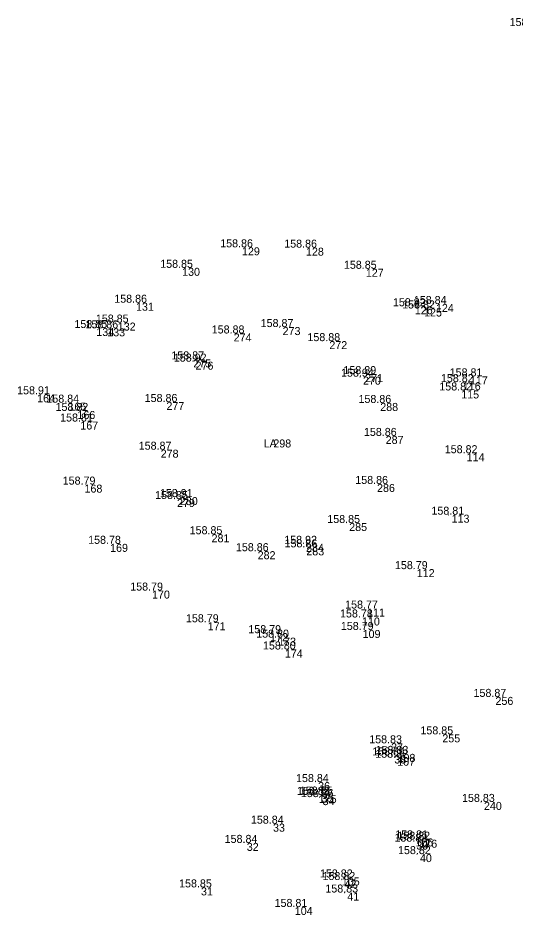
# Model space of a CAD drawing. Extents: x -583198 to -582878, y -1211024 to -1210637.
# Drawn here: x -583173.33 to -583157.8, y -1210989.22 to -1210961.21 of the extents above; entities that cross this region are included whole.
import ezdxf

# ---------------------------------------------------------------- set-up
doc = ezdxf.new("R2010")
doc.units = 0
for name, color, linetype in [('1   Kódy', 7, 'Continuous'), ('4   Body podrobné', 7, 'Continuous'), ('5   Body podrobné - čísla', 7, 'Continuous'), ('6   Body podrobné - výšky', 7, 'Continuous')]:
    doc.layers.add(name, color=color, linetype=linetype)

msp = doc.modelspace()

# ---------------------------------------------------------------- linework, layer by layer
at = {"layer": '4   Body podrobné'}
for p, q in [((-583166.42, -1210968.37), (-583166.419, -1210968.37)), ((-583164.42, -1210968.38), (-583164.419, -1210968.38)), ((-583168.29, -1210969.01), (-583168.289, -1210969.01)), ((-583162.55, -1210969.04), (-583162.549, -1210969.04)), ((-583169.73, -1210970.1), (-583169.729, -1210970.1)), ((-583161.02, -1210970.21), (-583161.019, -1210970.21)), ((-583160.36, -1210970.14), (-583160.359, -1210970.14)), ((-583160.73, -1210970.28), (-583160.729, -1210970.28)), ((-583170.3, -1210970.72), (-583170.299, -1210970.72)), ((-583170.97, -1210970.89), (-583170.969, -1210970.89)), ((-583170.63, -1210970.9), (-583170.629, -1210970.9)), ((-583165.15, -1210970.86), (-583165.149, -1210970.86)), ((-583166.68, -1210971.06), (-583166.679, -1210971.06)), ((-583163.69, -1210971.3), (-583163.689, -1210971.3)), ((-583167.94, -1210971.87), (-583167.939, -1210971.87)), ((-583167.87, -1210971.94), (-583167.869, -1210971.94)), ((-583162.64, -1210972.41), (-583162.639, -1210972.41)), ((-583162.57, -1210972.33), (-583162.569, -1210972.33)), ((-583159.3, -1210972.4), (-583159.299, -1210972.4)), ((-583159.52, -1210972.58), (-583159.519, -1210972.58)), ((-583172.82, -1210972.96), (-583172.819, -1210972.96)), ((-583159.57, -1210972.84), (-583159.569, -1210972.84)), ((-583171.84, -1210973.22), (-583171.839, -1210973.22)), ((-583168.78, -1210973.2), (-583168.779, -1210973.2)), ((-583162.1, -1210973.23), (-583162.099, -1210973.23)), ((-583171.56, -1210973.48), (-583171.559, -1210973.48)), ((-583171.47, -1210973.81), (-583171.469, -1210973.81)), ((-583165.44, -1210974.37), (-583165.439, -1210974.37)), ((-583161.93, -1210974.26), (-583161.929, -1210974.26)), ((-583168.96, -1210974.69), (-583168.959, -1210974.69)), ((-583159.4, -1210974.8), (-583159.399, -1210974.8)), ((-583171.34, -1210975.78), (-583171.339, -1210975.78)), ((-583162.2, -1210975.76), (-583162.199, -1210975.76)), ((-583168.45, -1210976.23), (-583168.449, -1210976.23)), ((-583168.36, -1210976.17), (-583168.359, -1210976.17)), ((-583159.87, -1210976.72), (-583159.869, -1210976.72)), ((-583163.07, -1210976.98), (-583163.069, -1210976.98)), ((-583167.37, -1210977.33), (-583167.369, -1210977.33)), ((-583170.54, -1210977.63), (-583170.539, -1210977.63)), ((-583164.42, -1210977.63), (-583164.419, -1210977.63)), ((-583164.41, -1210977.74), (-583164.409, -1210977.74)), ((-583165.93, -1210977.86), (-583165.929, -1210977.86)), ((-583160.96, -1210978.42), (-583160.959, -1210978.42)), ((-583169.23, -1210979.09), (-583169.229, -1210979.09)), ((-583162.51, -1210979.65), (-583162.509, -1210979.65)), ((-583162.67, -1210979.93), (-583162.669, -1210979.93)), ((-583167.49, -1210980.08), (-583167.489, -1210980.08)), ((-583165.54, -1210980.42), (-583165.539, -1210980.42)), ((-583165.29, -1210980.56), (-583165.289, -1210980.56)), ((-583162.65, -1210980.32), (-583162.649, -1210980.32)), ((-583165.08, -1210980.93), (-583165.079, -1210980.93)), ((-583158.5, -1210982.41), (-583158.499, -1210982.41)), ((-583160.16, -1210983.58), (-583160.159, -1210983.58)), ((-583161.76, -1210983.86), (-583161.759, -1210983.86)), ((-583161.56, -1210984.19), (-583161.559, -1210984.19)), ((-583161.66, -1210984.24), (-583161.659, -1210984.24)), ((-583161.57, -1210984.31), (-583161.569, -1210984.31)), ((-583164.04, -1210985.07), (-583164.039, -1210985.07)), ((-583164.02, -1210985.47), (-583164.019, -1210985.47)), ((-583163.93, -1210985.46), (-583163.929, -1210985.46)), ((-583163.9, -1210985.54), (-583163.899, -1210985.54)), ((-583158.86, -1210985.69), (-583158.859, -1210985.69)), ((-583165.45, -1210986.37), (-583165.449, -1210986.37)), ((-583166.27, -1210986.97), (-583166.269, -1210986.97)), ((-583161, -1210986.83), (-583160.999, -1210986.83)), ((-583160.97, -1210986.93), (-583160.969, -1210986.93)), ((-583160.88, -1210986.87), (-583160.879, -1210986.87)), ((-583160.86, -1210987.32), (-583160.859, -1210987.32)), ((-583163.3, -1210988.05), (-583163.299, -1210988.05)), ((-583163.22, -1210988.13), (-583163.219, -1210988.13)), ((-583167.7, -1210988.36), (-583167.699, -1210988.36)), ((-583163.13, -1210988.52), (-583163.129, -1210988.52)), ((-583164.77, -1210988.97), (-583164.769, -1210988.97))]:
    msp.add_line(p, q, dxfattribs=at)

# ---------------------------------------------------------------- texts
at = {"layer": '1   Kódy'}
msp.add_text('LA', height=0.25, dxfattribs=at).set_placement((-583165.65, -1210974.62))
at = {"layer": '5   Body podrobné - čísla'}
for s, p in [(' 129', (-583166.42, -1210968.62)), (' 128', (-583164.42, -1210968.63)), (' 130', (-583168.29, -1210969.26)), (' 127', (-583162.55, -1210969.29)), (' 131', (-583169.73, -1210970.35)), (' 126', (-583161.02, -1210970.46)), (' 124', (-583160.36, -1210970.39)), (' 125', (-583160.73, -1210970.53)), (' 132', (-583170.3, -1210970.97)), (' 134', (-583170.97, -1210971.14)), (' 133', (-583170.63, -1210971.15)), (' 273', (-583165.15, -1210971.11)), (' 274', (-583166.68, -1210971.31)), (' 272', (-583163.69, -1210971.55)), (' 275', (-583167.94, -1210972.12)), (' 276', (-583167.87, -1210972.19)), (' 270', (-583162.64, -1210972.66)), (' 271', (-583162.57, -1210972.58)), (' 117', (-583159.3, -1210972.65)), (' 116', (-583159.52, -1210972.83)), (' 164', (-583172.82, -1210973.21)), (' 115', (-583159.57, -1210973.09)), (' 165', (-583171.84, -1210973.47)), (' 277', (-583168.78, -1210973.45)), (' 288', (-583162.1, -1210973.48)), (' 166', (-583171.56, -1210973.73)), (' 167', (-583171.47, -1210974.06)), (' 298', (-583165.44, -1210974.62)), (' 287', (-583161.93, -1210974.51)), (' 278', (-583168.96, -1210974.94)), (' 114', (-583159.4, -1210975.05)), (' 168', (-583171.34, -1210976.03)), (' 286', (-583162.2, -1210976.01)), (' 279', (-583168.45, -1210976.48)), (' 280', (-583168.36, -1210976.42)), (' 113', (-583159.87, -1210976.97)), (' 285', (-583163.07, -1210977.23)), (' 281', (-583167.37, -1210977.58)), (' 169', (-583170.54, -1210977.88)), (' 284', (-583164.42, -1210977.88)), (' 283', (-583164.41, -1210977.99)), (' 282', (-583165.93, -1210978.11)), (' 112', (-583160.96, -1210978.67)), (' 170', (-583169.23, -1210979.34)), (' 111', (-583162.51, -1210979.9)), (' 110', (-583162.67, -1210980.18)), (' 171', (-583167.49, -1210980.33)), (' 172', (-583165.54, -1210980.67)), (' 173', (-583165.29, -1210980.81)), (' 109', (-583162.65, -1210980.57)), (' 174', (-583165.08, -1210981.18)), (' 256', (-583158.5, -1210982.66)), (' 255', (-583160.16, -1210983.83)), (' 37', (-583161.76, -1210984.11)), (' 108', (-583161.56, -1210984.44)), (' 38', (-583161.66, -1210984.49)), (' 107', (-583161.57, -1210984.56)), (' 36', (-583164.04, -1210985.32)), (' 175', (-583164.02, -1210985.72)), (' 35', (-583163.93, -1210985.71)), (' 34', (-583163.9, -1210985.79)), (' 240', (-583158.86, -1210985.94)), (' 33', (-583165.45, -1210986.62)), (' 32', (-583166.27, -1210987.22)), (' 106', (-583161, -1210987.08)), (' 39', (-583160.97, -1210987.18)), (' 176', (-583160.88, -1210987.12)), (' 40', (-583160.86, -1210987.57)), (' 105', (-583163.3, -1210988.3)), (' 42', (-583163.22, -1210988.38)), (' 31', (-583167.7, -1210988.61)), (' 41', (-583163.13, -1210988.77)), (' 104', (-583164.77, -1210989.22))]:
    msp.add_text(s, height=0.25, dxfattribs=at).set_placement(p)
at = {"layer": '6   Body podrobné - výšky'}
for s, p in [('158.86', (-583157.967, -1210961.46)), ('158.86', (-583167.007, -1210968.37)), ('158.86', (-583165.007, -1210968.38)), ('158.85', (-583168.882, -1210969.01)), ('158.85', (-583163.142, -1210969.04)), ('158.86', (-583170.317, -1210970.1)), ('158.84', (-583160.958, -1210970.14)), ('158.82', (-583161.612, -1210970.21)), ('158.82', (-583161.322, -1210970.28)), ('158.85', (-583170.892, -1210970.72)), ('158.85', (-583171.562, -1210970.89)), ('158.86', (-583171.217, -1210970.9)), ('158.87', (-583165.743, -1210970.86)), ('158.88', (-583167.272, -1210971.06)), ('158.88', (-583164.282, -1210971.3)), ('158.87', (-583168.533, -1210971.87)), ('158.92', (-583168.457, -1210971.94)), ('158.94', (-583163.232, -1210972.41)), ('158.89', (-583163.157, -1210972.33)), ('158.81', (-583159.838, -1210972.4)), ('158.82', (-583160.112, -1210972.58)), ('158.91', (-583173.352, -1210972.96)), ('158.82', (-583160.162, -1210972.84)), ('158.84', (-583172.438, -1210973.22)), ('158.86', (-583169.367, -1210973.2)), ('158.86', (-583162.687, -1210973.23)), ('158.82', (-583172.152, -1210973.48)), ('158.81', (-583172.008, -1210973.81)), ('158.86', (-583162.517, -1210974.26)), ('158.87', (-583169.553, -1210974.69)), ('158.82', (-583159.992, -1210974.8)), ('158.79', (-583171.928, -1210975.78)), ('158.86', (-583162.787, -1210975.76)), ('158.85', (-583169.042, -1210976.23)), ('158.91', (-583168.892, -1210976.17)), ('158.81', (-583160.408, -1210976.72)), ('158.85', (-583163.662, -1210976.98)), ('158.85', (-583167.962, -1210977.33)), ('158.78', (-583171.133, -1210977.63)), ('158.92', (-583165.007, -1210977.63)), ('158.86', (-583164.997, -1210977.74)), ('158.86', (-583166.517, -1210977.86)), ('158.79', (-583161.548, -1210978.42)), ('158.79', (-583169.818, -1210979.09)), ('158.77', (-583163.104, -1210979.65)), ('158.78', (-583163.263, -1210979.93)), ('158.79', (-583168.078, -1210980.08)), ('158.79', (-583166.128, -1210980.42)), ('158.79', (-583163.238, -1210980.32)), ('158.80', (-583165.882, -1210980.56)), ('158.80', (-583165.672, -1210980.93)), ('158.87', (-583159.093, -1210982.41)), ('158.85', (-583160.752, -1210983.58)), ('158.83', (-583162.352, -1210983.86)), ('158.83', (-583162.152, -1210984.19)), ('158.84', (-583162.258, -1210984.24)), ('158.82', (-583162.162, -1210984.31)), ('158.84', (-583164.638, -1210985.07)), ('158.83', (-583164.612, -1210985.47)), ('158.85', (-583164.522, -1210985.46)), ('158.86', (-583164.487, -1210985.54)), ('158.83', (-583159.452, -1210985.69)), ('158.84', (-583166.048, -1210986.37)), ('158.84', (-583166.868, -1210986.97)), ('158.82', (-583161.562, -1210986.93)), ('158.81', (-583161.538, -1210986.83)), ('158.82', (-583161.472, -1210986.87)), ('158.82', (-583161.452, -1210987.32)), ('158.82', (-583163.892, -1210988.05)), ('158.85', (-583168.292, -1210988.36)), ('158.82', (-583163.812, -1210988.13)), ('158.83', (-583163.722, -1210988.52)), ('158.81', (-583165.308, -1210988.97))]:
    msp.add_text(s, height=0.25, dxfattribs=at).set_placement(p)

doc.saveas('drawing.dxf')
